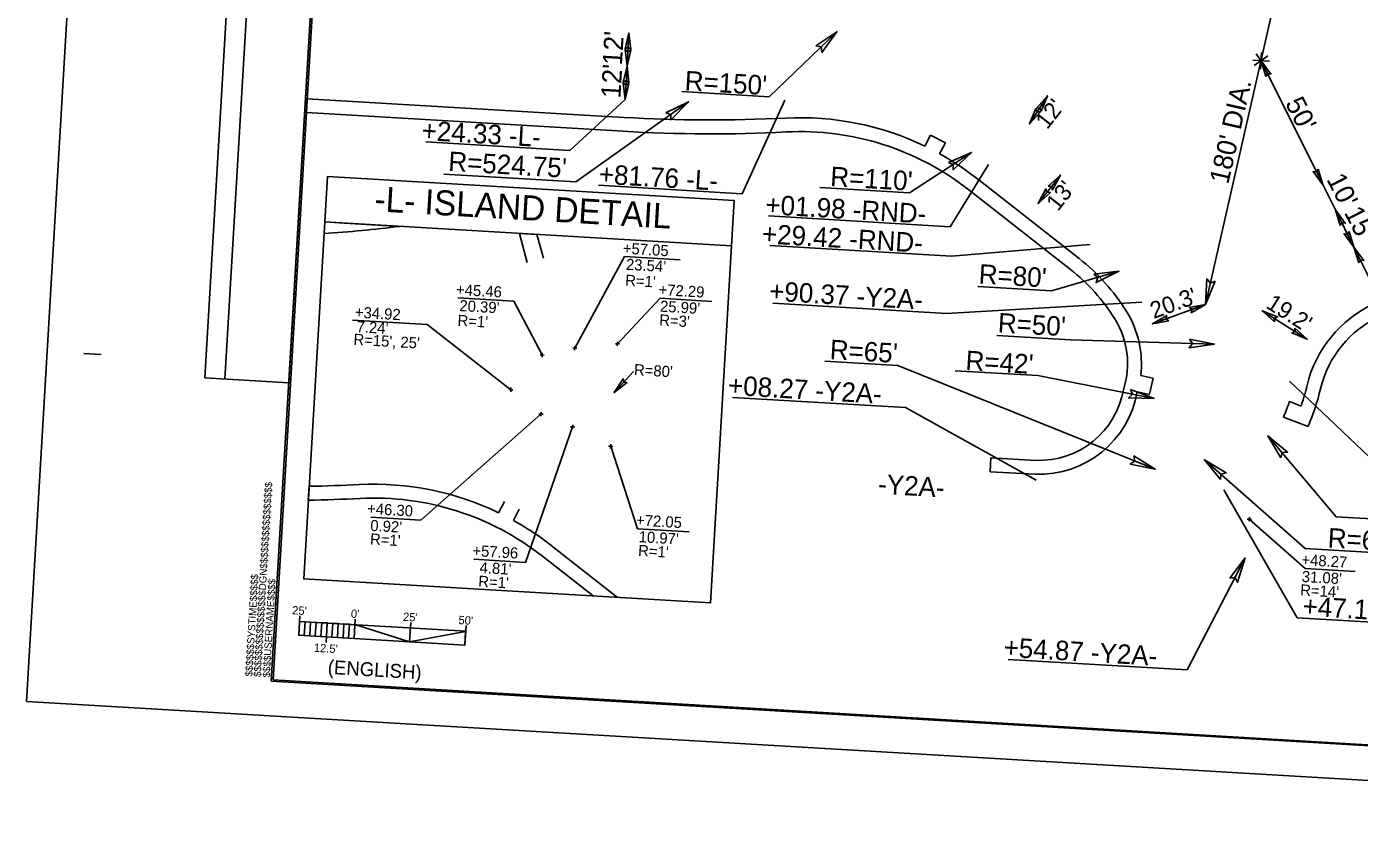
# Model space of a CAD drawing. Extents: x 2012744 to 2013625, y 444638 to 445237.
# Drawn here: x 2012743.6 to 2013223.7, y 444637.7 to 444930.6 of the extents above; entities that cross this region are included whole.
import ezdxf

# ---------------------------------------------------------------- set-up
doc = ezdxf.new("R2010")
doc.units = 0
for name, color, linetype in [('Old_Level_1', 7, 'Continuous'), ('Old_Level_10', 7, 'Continuous'), ('Prop Conc 4in Sidewalk', 7, 'Continuous'), ('Prop Dimension', 7, 'Continuous'), ('Prop Dimension Text', 7, 'Continuous'), ('Prop PHM English Scale CELL', 7, 'Continuous'), ('Prop Shade Medium', 7, 'Continuous'), ('Prop Terminator CELL', 7, 'Continuous'), ('Sheet Block Revision CELL', 7, 'Continuous'), ('Sheet Block System Information CELL', 7, 'Continuous'), ('Sheet Clip Boundary CELL', 7, 'Continuous'), ('Sheet Plan And Profile CELL', 7, 'Continuous'), ('Sheet Plot Border Outside CELL', 7, 'Continuous')]:
    doc.layers.add(name, color=color, linetype=linetype)

msp = doc.modelspace()

# ---------------------------------------------------------------- linework, layer by layer
at = {"layer": 'Old_Level_1'}
for points in [[(2012851, 444860.33), (2012997.56, 444851.69), (2012998.52, 444868.02), (2012851.96, 444876.66)], [(2012851, 444860.33), (2012997.56, 444851.69), (2012989.98, 444723.21), (2012843.42, 444731.85)]]:
    msp.add_lwpolyline(points, close=True, dxfattribs=at)
at = {"layer": 'Prop Conc 4in Sidewalk'}
for p, q in [((2013149.36, 444804.16), (2013144.94, 444805.08)), ((2013148.14, 444798.28), (2013143.7, 444799.21)), ((2013090.68, 444770.38), (2013090.95, 444775.37)), ((2013090.95, 444775.37), (2013107.1, 444774.5)), ((2013090.68, 444770.38), (2013106.92, 444769.5))]:
    msp.add_line(p, q, dxfattribs=at)
for centre, radius, start, end in [((2013077.42, 444789.28), 73.5, 31.8625, 51.9343), ((2013108.27, 444805.46), 35.98, 267.8497, 349.9973), ((2012868.72, 444662.43), 103.5, 64.2868, 92.9092), ((2012868.72, 444662.43), 98.5, 51.9343, 92.9092), ((2012868.72, 444662.43), 103.5, 51.9343, 60.9651)]:
    msp.add_arc(centre, radius, start, end, dxfattribs=at)
at = {"layer": 'Prop Dimension'}
for p, q in [((2013168.27, 444830.65), (2013208.29, 445006.14)), ((2012959.89, 444916.44), (2012960.59, 444928.42)), ((2013011.09, 444905.41), (2013035.53, 444928.8)), ((2013190.06, 444915.98), (2013186.5, 444920.81)), ((2013188.1, 444915.4), (2013188.46, 444921.39)), ((2012959.18, 444904.46), (2012959.89, 444916.44)), ((2013191.27, 444918.22), (2013185.28, 444918.57)), ((2013190.7, 444920.17), (2013185.86, 444916.62)), ((2013210.25, 444874.32), (2013188.28, 444918.4)), ((2012959.18, 444904.46), (2012939.27, 444886.12)), ((2012941.48, 444874.74), (2012982.09, 444903.61)), ((2013016.69, 444904.23), (2013001.4, 444870.51)), ((2013111.31, 444905.77), (2013104.91, 444895.61)), ((2012939.27, 444886.12), (2012887.47, 444889.17)), ((2013084.03, 444885.39), (2013061.65, 444870.79)), ((2013090.1, 444880.97), (2013076.34, 444858.64)), ((2013001.4, 444870.51), (2012949.6, 444873.57)), ((2013061.65, 444870.79), (2013029.37, 444872.69)), ((2013116, 444877.2), (2013107.98, 444866.97)), ((2013210.25, 444874.32), (2013215.05, 444864.7)), ((2013215.05, 444864.7), (2013221.74, 444851.27)), ((2013076.34, 444858.64), (2013010.86, 444862.5)), ((2013076.77, 444848.05), (2013011.29, 444851.91)), ((2013126.75, 444852.27), (2013076.77, 444848.05)), ((2013221.74, 444851.27), (2013228.43, 444837.85)), ((2012941.08, 444814.92), (2012958.98, 444847.92)), ((2012979.07, 444846.74), (2012958.98, 444847.92)), ((2013137.09, 444842.58), (2013112.78, 444835.49)), ((2013112.78, 444835.49), (2013086.27, 444837.05)), ((2012919.07, 444831.87), (2012898.98, 444833.06)), ((2012929.33, 444812.45), (2012919.07, 444831.87)), ((2012971.78, 444832.86), (2012956.44, 444816.46)), ((2012990.4, 444831.76), (2012971.78, 444832.86)), ((2013075.01, 444827.44), (2013012.46, 444831.13)), ((2013145.37, 444831.52), (2013075.01, 444827.44)), ((2013149.17, 444823.7), (2013168.27, 444830.65)), ((2012887.89, 444823.41), (2012861.03, 444824.99)), ((2013188.7, 444828.4), (2013204.92, 444818.13)), ((2012918.02, 444799.95), (2012887.89, 444823.41)), ((2013119.66, 444817.92), (2013093.15, 444819.48)), ((2013171.48, 444816.38), (2013119.66, 444817.92)), ((2013057.44, 444808.7), (2013031.14, 444810.25)), ((2012955.24, 444798.9), (2012962.28, 444806.51)), ((2013057.44, 444808.7), (2013150.16, 444771.29)), ((2013107.88, 444805.01), (2013078.08, 444806.77)), ((2013107.88, 444805.01), (2013149.78, 444796.8)), ((2013198.53, 444803), (2013240.71, 444762.87)), ((2013060.21, 444793.51), (2012997.86, 444797.19)), ((2012928.9, 444791.13), (2012885.58, 444752.95)), ((2013107.27, 444767.41), (2013060.21, 444793.51)), ((2012940.31, 444786.57), (2012923.35, 444737.8)), ((2013215.37, 444754.18), (2013190.77, 444783.35)), ((2012954.02, 444779.58), (2012963.62, 444749.89)), ((2013204.22, 444742.82), (2013167.91, 444774.74)), ((2013174.86, 444763.88), (2013201.3, 444717.81)), ((2012885.58, 444752.95), (2012867.56, 444754.01)), ((2013184.05, 444753.33), (2013204.21, 444735.58)), ((2013249.43, 444752.17), (2013215.37, 444754.18)), ((2012982.24, 444748.8), (2012963.62, 444749.89)), ((2012923.35, 444737.8), (2012904.73, 444738.9)), ((2013161.67, 444699.06), (2013182.53, 444739.41)), ((2013239.15, 444740.76), (2013204.22, 444742.82)), ((2013222.18, 444734.52), (2013204.21, 444735.58)), ((2013270.49, 444713.73), (2013201.3, 444717.81)), ((2013161.67, 444699.06), (2013097.13, 444702.86))]:
    msp.add_line(p, q, dxfattribs=at)
at = {"layer": 'Prop Dimension Text'}
for p, q in [((2012979.64, 444907.26), (2013011.09, 444905.41)), ((2012893.89, 444877.54), (2012941.48, 444874.74)), ((2012941.08, 444814.92), (2012940.33, 444814.97)), ((2012941.12, 444815.67), (2012941.03, 444814.17)), ((2012956.44, 444816.46), (2012955.69, 444816.5)), ((2012956.48, 444817.21), (2012956.39, 444815.71)), ((2012956.44, 444816.46), (2012957.19, 444816.42)), ((2012929.33, 444812.45), (2012928.58, 444812.5)), ((2012929.37, 444813.2), (2012929.28, 444811.7)), ((2012929.33, 444812.45), (2012930.07, 444812.41)), ((2012941.08, 444814.92), (2012941.83, 444814.88)), ((2012918.07, 444800.7), (2012917.98, 444799.2)), ((2012918.02, 444799.95), (2012917.27, 444799.99)), ((2012918.02, 444799.95), (2012918.77, 444799.9)), ((2012928.9, 444791.13), (2012928.15, 444791.18)), ((2012928.95, 444791.88), (2012928.86, 444790.39)), ((2012928.9, 444791.13), (2012929.65, 444791.09)), ((2012940.31, 444786.57), (2012939.57, 444786.61)), ((2012940.36, 444787.31), (2012940.27, 444785.82)), ((2012940.31, 444786.57), (2012941.06, 444786.52)), ((2012954.02, 444779.58), (2012953.27, 444779.63)), ((2012954.06, 444780.33), (2012953.98, 444778.83)), ((2012954.02, 444779.58), (2012954.77, 444779.54)), ((2013184.05, 444753.33), (2013183.31, 444753.37)), ((2013184.1, 444754.08), (2013184.01, 444752.58)), ((2013184.05, 444753.33), (2013184.8, 444753.28))]:
    msp.add_line(p, q, dxfattribs=at)
at = {"layer": 'Prop PHM English Scale CELL'}
for p, q in [((2012842.05, 444718.95), (2012842.05, 444718.95)), ((2012842.03, 444718.55), (2012841.62, 444711.56)), ((2012841.91, 444716.55), (2012841.62, 444711.56)), ((2012901.81, 444713.02), (2012841.91, 444716.55)), ((2012851.9, 444715.97), (2012851.48, 444708.98)), ((2012862, 444717.37), (2012861.58, 444710.35)), ((2012881.96, 444716.2), (2012881.55, 444709.21)), ((2012881.98, 444716.6), (2012881.98, 444716.6)), ((2012901.93, 444715.02), (2012901.51, 444708.03)), ((2012901.95, 444715.42), (2012901.95, 444715.42)), ((2012841.62, 444711.56), (2012901.51, 444708.03)), ((2012901.51, 444708.03), (2012901.81, 444713.02))]:
    msp.add_line(p, q, dxfattribs=at)
for points in [[(2012843.91, 444716.44), (2012841.91, 444716.55), (2012841.62, 444711.56), (2012843.62, 444711.45)], [(2012845.91, 444716.32), (2012847.9, 444716.2), (2012847.61, 444711.21), (2012845.61, 444711.33)], [(2012849.9, 444716.08), (2012851.9, 444715.97), (2012851.6, 444710.97), (2012849.6, 444711.09)], [(2012853.89, 444715.85), (2012855.89, 444715.73), (2012855.59, 444710.74), (2012853.6, 444710.86)], [(2012857.89, 444715.61), (2012859.88, 444715.5), (2012859.59, 444710.5), (2012857.59, 444710.62)], [(2012861.88, 444715.38), (2012881.55, 444709.17), (2012861.58, 444710.35)], [(2012881.55, 444709.17), (2012901.7, 444712.95), (2012901.51, 444708.03)]]:
    msp.add_lwpolyline(points, close=True, dxfattribs=at)
at = {"layer": 'Prop Shade Medium'}
for p, q in [((2012844.41, 444899.71), (2012844.7, 444904.7)), ((2012844.7, 444904.7), (2012958.8, 444897.97)), ((2012958.5, 444892.98), (2012844.41, 444899.71)), ((2013067.18, 444887.62), (2013069.25, 444891.62)), ((2013069.25, 444891.62), (2013074.58, 444888.86)), ((2013069.25, 444891.62), (2013074.58, 444888.86)), ((2013074.58, 444888.86), (2013072.51, 444884.86)), ((2013086.09, 444875.85), (2013122.74, 444847.15)), ((2013119.66, 444843.22), (2013083.01, 444871.92)), ((2012850.75, 444856.23), (2012851, 444860.33)), ((2012851, 444860.33), (2012857.95, 444859.92)), ((2012857.95, 444859.92), (2012877.92, 444858.74)), ((2012921.13, 444856.2), (2012923.98, 444845.69)), ((2012927.44, 444855.82), (2012921.13, 444856.2)), ((2012929.77, 444847.26), (2012927.44, 444855.82)), ((2013144.94, 444805.08), (2013149.36, 444804.16)), ((2013149.37, 444804.16), (2013148.14, 444798.29)), ((2013148.14, 444798.28), (2013143.7, 444799.21)), ((2013202.7, 444794.07), (2013198.49, 444795.68)), ((2013196.35, 444790.07), (2013205.22, 444786.67)), ((2013090.68, 444770.38), (2013090.95, 444775.37)), ((2013090.95, 444775.37), (2013107.1, 444774.5)), ((2013106.92, 444769.5), (2013090.68, 444770.38)), ((2012845.09, 444760.18), (2012845.39, 444765.19)), ((2012913.63, 444755.68), (2012915.7, 444759.68)), ((2012921.03, 444756.92), (2012918.96, 444752.92)), ((2012932.54, 444743.92), (2012956.46, 444725.18)), ((2012947.69, 444725.7), (2012929.45, 444739.98))]:
    msp.add_line(p, q, dxfattribs=at)
for centre, radius, start, end in [((2012990.06, 445428.3), 531.25, 266.6264, 272.9092), ((2013022.28, 444794.37), 103.5, 64.2868, 92.9092), ((2012990.06, 445428.3), 536.25, 266.6264, 272.9092), ((2013022.28, 444794.37), 98.5, 51.9343, 92.9092), ((2013022.28, 444794.37), 103.5, 51.9343, 60.9651), ((2012829.78, 445231.65), 376, 273.1983, 277.356), ((2013077.42, 444789.28), 73.5, 31.8625, 51.9343), ((2013077.42, 444789.28), 68.5, 31.8625, 51.9343), ((2013247.16, 444791.38), 43.5, 114.8702, 166.5654), ((2013109.7, 444809.34), 30.5, 342.6037, 31.8625), ((2013109.7, 444809.34), 35.5, 353.0961, 31.8625), ((2013247.16, 444791.38), 38.5, 114.8702, 166.5654), ((2013125.58, 444820.42), 81.5, 341.1323, 346.5651), ((2013108.27, 444805.46), 35.98, 267.8497, 349.9973), ((2013108.27, 444805.46), 30.98, 267.8497, 350.2796), ((2013125.58, 444820.42), 86.5, 337.0368, 346.5651), ((2013125.58, 444820.42), 77, 336.789, 341.2544), ((2012836.51, 445296.36), 531.25, 270.9578, 272.9092), ((2012868.72, 444662.43), 103.5, 64.2868, 92.9092), ((2012836.51, 445296.36), 536.25, 270.9173, 272.9092), ((2012868.72, 444662.43), 98.5, 51.9343, 92.9092), ((2012868.72, 444662.43), 103.5, 51.9343, 60.9651)]:
    msp.add_arc(centre, radius, start, end, dxfattribs=at)
at = {"layer": 'Prop Terminator CELL'}
for points in [[(2012959.24, 444922.64), (2012960.59, 444928.42), (2012961.28, 444922.48), (2012960.29, 444923.29)], [(2013027.96, 444923.7), (2013035.53, 444928.8), (2013030.1, 444921.39), (2013029.83, 444923.34)], [(2012961.24, 444922.22), (2012959.89, 444916.44), (2012959.19, 444922.37), (2012960.19, 444921.56)], [(2012958.54, 444910.66), (2012959.89, 444916.44), (2012960.58, 444910.51), (2012959.58, 444911.31)], [(2013189.99, 444912.71), (2013188.28, 444918.4), (2013191.83, 444913.6), (2013190.57, 444913.8)], [(2012960.53, 444910.24), (2012959.18, 444904.46), (2012958.49, 444910.39), (2012959.48, 444909.59)], [(2012973.86, 444899.66), (2012982.09, 444903.61), (2012975.64, 444897.06), (2012975.65, 444899.03)], [(2013107.34, 444901.35), (2013111.31, 444905.77), (2013109.05, 444900.24), (2013108.57, 444901.42)], [(2013108.88, 444900.03), (2013104.91, 444895.61), (2013107.17, 444901.15), (2013107.65, 444899.96)], [(2013075.65, 444881.78), (2013084.03, 444885.39), (2013077.33, 444879.11), (2013077.42, 444881.08)], [(2013208.88, 444879.33), (2013210.59, 444873.65), (2013207.03, 444878.45), (2013208.3, 444878.24)], [(2013111.6, 444873.22), (2013116, 444877.2), (2013113.19, 444871.93), (2013112.83, 444873.16)], [(2013112.38, 444870.95), (2013107.98, 444866.97), (2013110.79, 444872.24), (2013111.15, 444871.01)], [(2013216.76, 444859.01), (2013215.05, 444864.7), (2013218.6, 444859.9), (2013217.34, 444860.1)], [(2013220.03, 444856.96), (2013221.74, 444851.27), (2013218.19, 444856.07), (2013219.45, 444855.87)], [(2013223.45, 444845.59), (2013221.74, 444851.27), (2013225.3, 444846.47), (2013224.03, 444846.68)], [(2013128.01, 444841.55), (2013137.09, 444842.58), (2013128.85, 444838.51), (2013129.5, 444840.37)], [(2013171.78, 444839.08), (2013168.27, 444830.65), (2013168.72, 444839.83), (2013170.03, 444838.35)], [(2013162.43, 444829.6), (2013168.27, 444830.65), (2013163.1, 444827.66), (2013163.45, 444828.89)], [(2013155.01, 444824.75), (2013149.17, 444823.7), (2013154.34, 444826.69), (2013153.99, 444825.46)], [(2013193.1, 444824.42), (2013188.7, 444828.4), (2013194.23, 444826.13), (2013193.04, 444825.65)], [(2013200.51, 444822.11), (2013204.92, 444818.13), (2013199.39, 444820.4), (2013200.58, 444820.88)], [(2013162.53, 444818.2), (2013171.48, 444816.38), (2013162.39, 444815.05), (2013163.59, 444816.61)], [(2012959.95, 444802.51), (2012955.24, 444798.9), (2012958.47, 444803.92), (2012958.72, 444802.67)], [(2013141.25, 444800.05), (2013149.78, 444796.8), (2013140.59, 444796.97), (2013142.03, 444798.32)], [(2013195.39, 444775.47), (2013190.77, 444783.35), (2013197.83, 444777.46), (2013195.87, 444777.31)], [(2013142.4, 444776.09), (2013150.16, 444771.29), (2013141.17, 444773.19), (2013142.84, 444774.24)], [(2013173.65, 444767.63), (2013167.91, 444774.74), (2013175.76, 444769.97), (2013173.84, 444769.52)], [(2013177.02, 444732.13), (2013182.53, 444739.41), (2013179.8, 444730.64), (2013178.91, 444732.39)]]:
    msp.add_lwpolyline(points, close=True, dxfattribs=at)
at = {"layer": 'Sheet Block Revision CELL'}
msp.add_line((2012815.07, 444803.74), (2012838.34, 445198.38), dxfattribs=at)
msp.add_lwpolyline([(2012807.81, 444804.17), (2012831.07, 445198.81), (2012861.3, 445197.03), (2012838.03, 444802.39)], close=True, dxfattribs=at)
at = {"layer": 'Sheet Block System Information CELL'}
msp.add_line((2012831.71, 444695.07), (2012831.71, 444695.07), dxfattribs=at)
at = {"layer": 'Sheet Clip Boundary CELL'}
for points in [[(2013605.95, 445084.18), (2013506.09, 445090.07), (2013509.49, 445147.63), (2013409.64, 445153.51), (2013411.6, 445186.8), (2012862.6, 445219.16), (2012831.71, 444695.07), (2013580.41, 444650.94)], [(2012832.37, 444695.56), (2012863.22, 445218.85), (2013411.41, 445186.54), (2013409.45, 445153.34), (2013509.31, 445147.45), (2013505.92, 445089.85), (2013605.86, 445083.96), (2013580.34, 444651.05)]]:
    msp.add_lwpolyline(points, close=True, dxfattribs=at)
at = {"layer": 'Sheet Plan And Profile CELL'}
for p, q in [((2012764.28, 444813), (2012770.52, 444812.63)), ((2012831.71, 444695.07), (2012831.71, 444695.07)), ((2012831.71, 444695.07), (2012831.71, 444695.07)), ((2012831.71, 444695.07), (2012831.71, 444695.07)), ((2012831.71, 444695.07), (2012831.71, 444695.07)), ((2012831.71, 444695.07), (2012831.71, 444695.07))]:
    msp.add_line(p, q, dxfattribs=at)
msp.add_lwpolyline([(2013611.3, 445175.03), (2012862.6, 445219.16), (2012831.71, 444695.07), (2013580.41, 444650.94)], close=True, dxfattribs=at)
at = {"layer": 'Sheet Plot Border Outside CELL'}
msp.add_lwpolyline([(2012743.62, 444687.74), (2013592.15, 444637.73), (2013624.51, 445186.77), (2012775.99, 445236.79)], close=True, dxfattribs=at)

# ---------------------------------------------------------------- texts
at = {"layer": 'Old_Level_10'}
for s, p in [('+57.05', (2012958.28, 444848.94)), ("23.54'", (2012959.42, 444843.13)), ("R=1'", (2012959.14, 444837.41)), ('+45.46', (2012898.21, 444834.09)), ('+72.29', (2012971.17, 444834.05)), ('+34.92', (2012861.76, 444825.93)), ("20.39'", (2012899.42, 444828.27)), ("25.99'", (2012971.69, 444828.06)), ("7.24'", (2012862.37, 444820.67)), ("R=1'", (2012898.74, 444822.95)), ("R=3'", (2012971.41, 444823.11)), ("R=15', 25'", (2012861.26, 444816.14)), ("R=80'", (2012962.31, 444805.23)), ('+46.30', (2012866.18, 444755.24)), ("0.92'", (2012867.32, 444749.14)), ('+72.05', (2012963.06, 444751.08)), ("R=1'", (2012867.23, 444744.26)), ("10.97'", (2012964, 444745.07)), ('+57.96', (2012904.1, 444740.09)), ("R=1'", (2012963.8, 444740.12)), ('+48.27', (2013202.74, 444736.81)), ("4.81'", (2012906.69, 444733.98)), ("31.08'", (2013202.87, 444730.77)), ("R=1'", (2012906.22, 444729.04)), ("R=14'", (2013202.3, 444725.92))]:
    msp.add_text(s, height=4, rotation=356.6264, dxfattribs=at).set_placement(p)
at = {"layer": 'Prop Dimension'}
for s, height, p in [('-L- ISLAND DETAIL', 9, (2012868.75, 444864.22)), ('-Y2A- ', 7, (2013050.19, 444762.56))]:
    msp.add_text(s, height=height, rotation=356.6264, dxfattribs=at).set_placement(p)
at = {"layer": 'Prop Dimension Text'}
for s, height, rotation, p in [("12'", 7, 86.6264, (2012958.05, 444916.63)), ("12'", 7, 86.6264, (2012957.5, 444904.74)), ("R=150'", 7, 356.6264, (2012980.52, 444907.76)), ("180' DIA.", 7, 77.155, (2013176.44, 444873.66)), ("12'", 6, 51.9343, (2013111.27, 444893.37)), ("50'", 7, 297.0252, (2013196.81, 444903.13)), ('+24.33 -L-', 7, 356.6264, (2012885.77, 444889.87)), ("R=524.75'", 7, 356.6264, (2012895.37, 444878.74)), ('+81.76 -L-', 7, 356.6264, (2012949.58, 444874.17)), ("R=110'", 7, 356.6264, (2013032.96, 444873.29)), ("10'", 7, 297.0252, (2013211.74, 444875.71)), ("13'", 6, 51.9343, (2013115.12, 444863.9)), ('+01.98 -RND-', 7, 356.6264, (2013009.58, 444863.18)), ("15'", 7, 297.0252, (2013218.06, 444863.79)), ('+29.42 -RND-', 7, 356.6264, (2013008.34, 444852.69)), ("R=80'", 7, 356.6264, (2013086.44, 444838.19)), ('+90.37 -Y2A-', 7, 356.6264, (2013010.94, 444832.07)), ("20.3'", 6, 19.9868, (2013149.65, 444825.4)), ("19.2'", 6, 327.6569, (2013189.66, 444829.67)), ("R=50'", 7, 356.6264, (2013093.32, 444820.62)), ("R=65'", 7, 356.6264, (2013032.79, 444811)), ("R=42'", 7, 356.6264, (2013081.69, 444807.05)), ('+08.27 -Y2A-', 7, 356.6264, (2012996.13, 444798.14)), ("R=60'", 7, 356.6264, (2013212.16, 444743.2)), ('+47.10 -Y2A-', 7, 356.6264, (2013203.08, 444718.63)), ('+54.87 -Y2A-', 7, 356.6264, (2013095.4, 444703.82))]:
    msp.add_text(s, height=height, rotation=rotation, dxfattribs=at).set_placement(p)
at = {"layer": 'Prop PHM English Scale CELL'}
for s, height, p in [("25'", 3, (2012839.21, 444719.12)), ("0'", 3, (2012860.36, 444717.87)), ("25'", 3, (2012879.14, 444716.76)), ("50'", 3, (2012899.11, 444715.59)), ("12.5'", 3, (2012847.01, 444705.61)), ('(ENGLISH)', 5, (2012851.99, 444697.68))]:
    msp.add_text(s, height=height, rotation=356.6264, dxfattribs=at).set_placement(p)
at = {"layer": 'Sheet Block System Information CELL'}
for s, p in [('$$$$$$$$$$$$$$$$DGN$$$$$$$$$$$$$$$$', (2012827.96, 444696.48)), ('$$$$$$SYSTIME$$$$$', (2012824.94, 444696.66)), ('$$$$USERNAME$$$$', (2012831.24, 444696.29))]:
    msp.add_text(s, height=2.625, rotation=86.6264, dxfattribs=at).set_placement(p)

doc.saveas('drawing.dxf')
